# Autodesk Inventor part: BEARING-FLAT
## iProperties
Created: 2007-08
Part Number: BEARING-FLAT
Material: Delrin, Black
Document SubType Name: Modeling
Density: 1.425 g/cm^3
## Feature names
1. Base1
